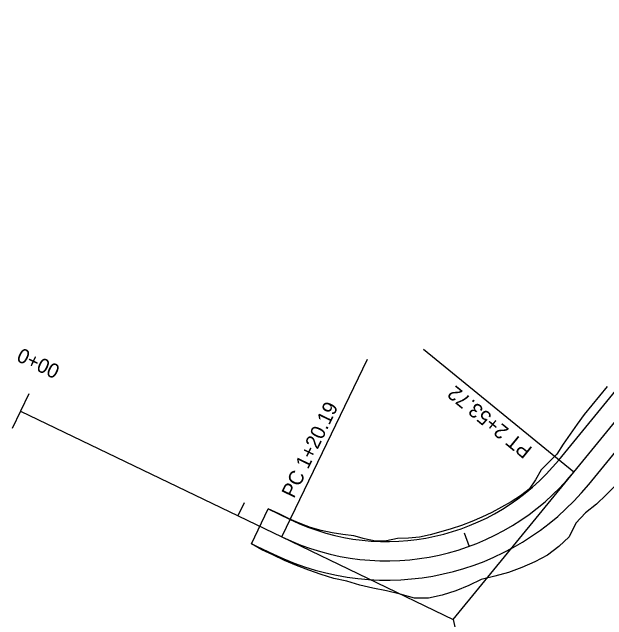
# Model space of a CAD drawing. Extents: x 1237212 to 1293764, y 379349 to 410301.
# Drawn here: x 1283048.4 to 1283294.7, y 404136.8 to 404388.6 of the extents above; entities that cross this region are included whole.
import ezdxf

# ---------------------------------------------------------------- set-up
doc = ezdxf.new("R2010")
doc.units = 0
for name, color, linetype in [('B-Sub-Footing', 7, 'Continuous'), ('B-Title Block (No Plot)', 7, 'Continuous'), ('R_Axis', 7, 'Continuous'), ('R_Exist Surface', 7, 'Continuous')]:
    doc.layers.add(name, color=color, linetype=linetype)

msp = doc.modelspace()

# ---------------------------------------------------------------- linework, layer by layer
for points in [[(1283055.31, 404230.5), (1283048.36, 404216.09)], [(1283144.53, 404185.31), (1283141.93, 404179.9)], [(1283235.68, 404172.89), (1283237.73, 404167.25)]]:
    msp.add_lwpolyline(points)
at = {"layer": 'B-Sub-Footing'}
for p, q in [((1283274.83, 404203.02), (1283414.32, 404373.62)), ((1283287.22, 404192.9), (1283427.73, 404364.74)), ((1283147.48, 404168.35), (1283154.43, 404182.76)), ((1283154.43, 404182.76), (1283163.59, 404178.35)), ((1283147.48, 404168.35), (1283156.65, 404163.94))]:
    msp.add_line(p, q, dxfattribs=at)
for radius in [92.09, 108.09]:
    msp.add_arc((1283203.55, 404261.32), radius, 244.2828, 320.7283, dxfattribs=at)
at = {"layer": 'B-Title Block (No Plot)'}
for p, q in [((1283281.02, 404197.96), (1283436.92, 404388.62)), ((1283281.02, 404197.96), (1283436.92, 404388.62)), ((1283051.83, 404223.3), (1283160.12, 404171.14)), ((1283051.83, 404223.3), (1283160.12, 404171.14))]:
    msp.add_line(p, q, dxfattribs=at)
msp.add_arc((1283203.55, 404261.31), 100.08, 244.2828, 320.7283, dxfattribs=at)
msp.add_arc((1283203.55, 404261.31), 100.08, 244.2828, 320.7283, dxfattribs=at)
at = {"layer": 'R_Axis'}
for p, q in [((1283231.13, 404136.94), (1283281.02, 404197.96)), ((1283160.12, 404171.14), (1283231.13, 404136.94))]:
    msp.add_line(p, q, dxfattribs=at)
for points in [[(1283281.02, 404197.96), (1283218.84, 404248.8)], [(1283160.12, 404171.14), (1283195.62, 404244.84)], [(1283231.13, 404136.94), (1283247.32, 404063.96)]]:
    msp.add_lwpolyline(points, dxfattribs=at)
at = {"layer": 'R_Exist Surface'}
for points in [[(1283294.93, 404233.45), (1283291.71, 404229.63), (1283288.49, 404225.8), (1283285.32, 404221.94), (1283282.44, 404217.84), (1283279.55, 404213.73), (1283276.67, 404209.63), (1283273.98, 404205.38), (1283270.72, 404202.08), (1283267.56, 404198.91), (1283265.24, 404194.85), (1283262.6, 404190.96)], [(1283298.04, 404192.16), (1283294.51, 404188.58), (1283290.41, 404184.74), (1283285.86, 404181.1), (1283281.94, 404176.88), (1283279.2, 404171.2), (1283274.88, 404167.18), (1283270.16, 404163.63), (1283264.97, 404160.79), (1283259.56, 404158.43), (1283254.02, 404156.45), (1283248.4, 404154.83), (1283242.74, 404153.5), (1283237.53, 404150.97), (1283232.12, 404148.82), (1283226.57, 404147.07), (1283220.88, 404145.73), (1283215.01, 404145.83), (1283209.13, 404147.36), (1283203.44, 404148.87), (1283197.86, 404149.86), (1283192.39, 404151.16), (1283187.05, 404152.75), (1283181.68, 404153.91), (1283176.45, 404155.52), (1283171.32, 404157.41), (1283166.23, 404159.3), (1283161.22, 404161.37), (1283156.34, 404163.69), (1283151.83, 404165.86), (1283147.48, 404168.35)], [(1283262.6, 404190.96), (1283258.99, 404188.13), (1283255.09, 404185.72), (1283251.12, 404183.45), (1283247.08, 404181.34), (1283242.98, 404179.37), (1283238.82, 404177.55), (1283234.6, 404175.88), (1283230.26, 404174.56), (1283225.93, 404173.21), (1283221.53, 404172.04), (1283217.08, 404171.09), (1283212.54, 404170.7), (1283208, 404170.44), (1283203.46, 404169.52), (1283198.87, 404169.45)], [(1283198.87, 404169.45), (1283194.35, 404170.42), (1283189.92, 404171.64), (1283185.4, 404172.14), (1283180.89, 404172.84), (1283176.42, 404173.8), (1283172.01, 404175.08), (1283167.71, 404176.67), (1283163.47, 404178.49), (1283158.97, 404180.67), (1283154.43, 404182.76)]]:
    msp.add_lwpolyline(points, dxfattribs=at)

# ---------------------------------------------------------------- texts
msp.add_text('0+00', height=6, rotation=334.2828).set_placement((1283049.75, 404244.28))
at = {"layer": 'R_Axis'}
for s, rotation, p in [('PT 2+53.72', 140.7283, (1283264.23, 404207.82)), ('PC 1+20.19', 64.2828, (1283165.11, 404186.85))]:
    msp.add_text(s, height=6, rotation=rotation, dxfattribs=at).set_placement(p)

doc.saveas('drawing.dxf')
